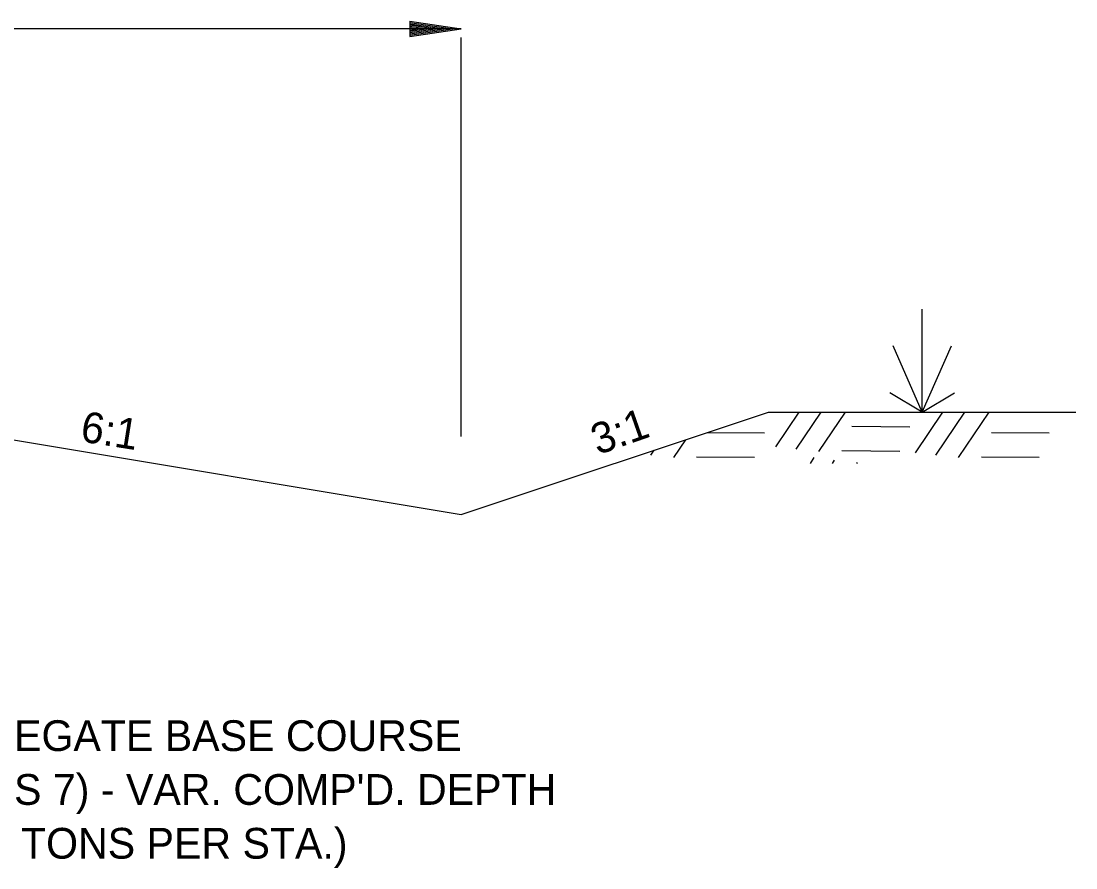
# Model space of a CAD drawing. Extents: x -900 to 15312, y 1857 to 2945.
# Drawn here: x -245.2 to -39.3, y 2127.5 to 2292.7 of the extents above; entities that cross this region are included whole.
import ezdxf

# ---------------------------------------------------------------- set-up
doc = ezdxf.new("R2010")
doc.units = 0
for name, color, linetype in [('R_Annotation', 7, 'Continuous'), ('R_Dimension', 7, 'Continuous'), ('R_Draft', 7, 'Continuous')]:
    doc.layers.add(name, color=color, linetype=linetype)

msp = doc.modelspace()

# ---------------------------------------------------------------- linework, layer by layer
at = {"layer": 'R_Annotation'}
for p, q in [((-319.31, 2223.11), (-159.31, 2196.44)), ((-159.31, 2196.44), (-99.31, 2216.44)), ((-99.31, 2216.44), (-39.31, 2216.44))]:
    msp.add_line(p, q, dxfattribs=at)
at = {"layer": 'R_Dimension'}
for p, q in [((-169.31, 2292.74), (-159.31, 2291.24)), ((-169.31, 2292.74), (-169.31, 2289.74)), ((-169.31, 2292.49), (-160.98, 2291.24)), ((-169.31, 2292.23), (-162.7, 2291.24)), ((-169.31, 2291.98), (-164.36, 2291.24)), ((-169.31, 2291.72), (-166.06, 2291.24)), ((-159.31, 2291.24), (-359.31, 2291.24)), ((-169.31, 2291.47), (-167.73, 2291.24)), ((-169.31, 2289.74), (-159.31, 2291.24)), ((-169.31, 2290.75), (-166.06, 2291.24)), ((-169.31, 2290.24), (-162.7, 2291.24)), ((-169.31, 2289.99), (-160.98, 2291.24)), ((-169.31, 2290.49), (-164.36, 2291.24)), ((-169.31, 2291), (-167.73, 2291.24)), ((-159.31, 2211.7), (-159.31, 2289.54)), ((-97.89, 2209.69), (-93.34, 2216.44)), ((-93.91, 2209.23), (-89.04, 2216.44)), ((-89.46, 2208.76), (-84.28, 2216.44)), ((-70.64, 2208.48), (-65.27, 2216.44)), ((-66.65, 2208.02), (-60.97, 2216.44)), ((-62.2, 2207.56), (-56.21, 2216.44)), ((-83.06, 2213.68), (-71.75, 2213.58)), ((-111.21, 2212.47), (-100.12, 2212.38)), ((-55.81, 2212.47), (-44.5, 2212.38)), ((-117.82, 2207.56), (-115.47, 2211.05)), ((-122.27, 2208.02), (-121.61, 2209)), ((-113.38, 2207.74), (-102.07, 2207.65)), ((-91.14, 2206.44), (-90.39, 2207.56)), ((-85.01, 2208.95), (-73.7, 2208.85)), ((-57.75, 2207.74), (-46.45, 2207.65)), ((-86.84, 2206.44), (-86.4, 2207.09)), ((-82.08, 2206.44), (-81.95, 2206.63))]:
    msp.add_line(p, q, dxfattribs=at)
at = {"layer": 'R_Draft'}
for q in [(-69.31, 2236.53), (-75, 2229.37), (-63.61, 2229.37), (-75.6, 2220.23), (-63.01, 2220.23)]:
    msp.add_line((-69.31, 2216.44), q, dxfattribs=at)

# ---------------------------------------------------------------- texts
at = {"layer": 'R_Annotation'}
for s, rotation, p in [('6:1', 350.9847, (-233.84, 2210.77)), ('3:1', 19.3394, (-132.65, 2208.04))]:
    msp.add_text(s, height=6, rotation=rotation, dxfattribs=at).set_placement(p)
for s, p in [('AGGREGATE BASE COURSE', (-270.21, 2150.32)), ("(CLASS 7) - VAR. COMP'D. DEPTH", (-270.21, 2139.82)), ('(53.50 TONS PER STA.)', (-270.21, 2129.32))]:
    msp.add_text(s, height=6, dxfattribs=at).set_placement(p)

doc.saveas('drawing.dxf')
